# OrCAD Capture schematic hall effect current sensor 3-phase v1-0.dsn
size B; title: 3-Phase Hall Effect Current Sensor; rev: 1; note: XM3 Dual Inverter
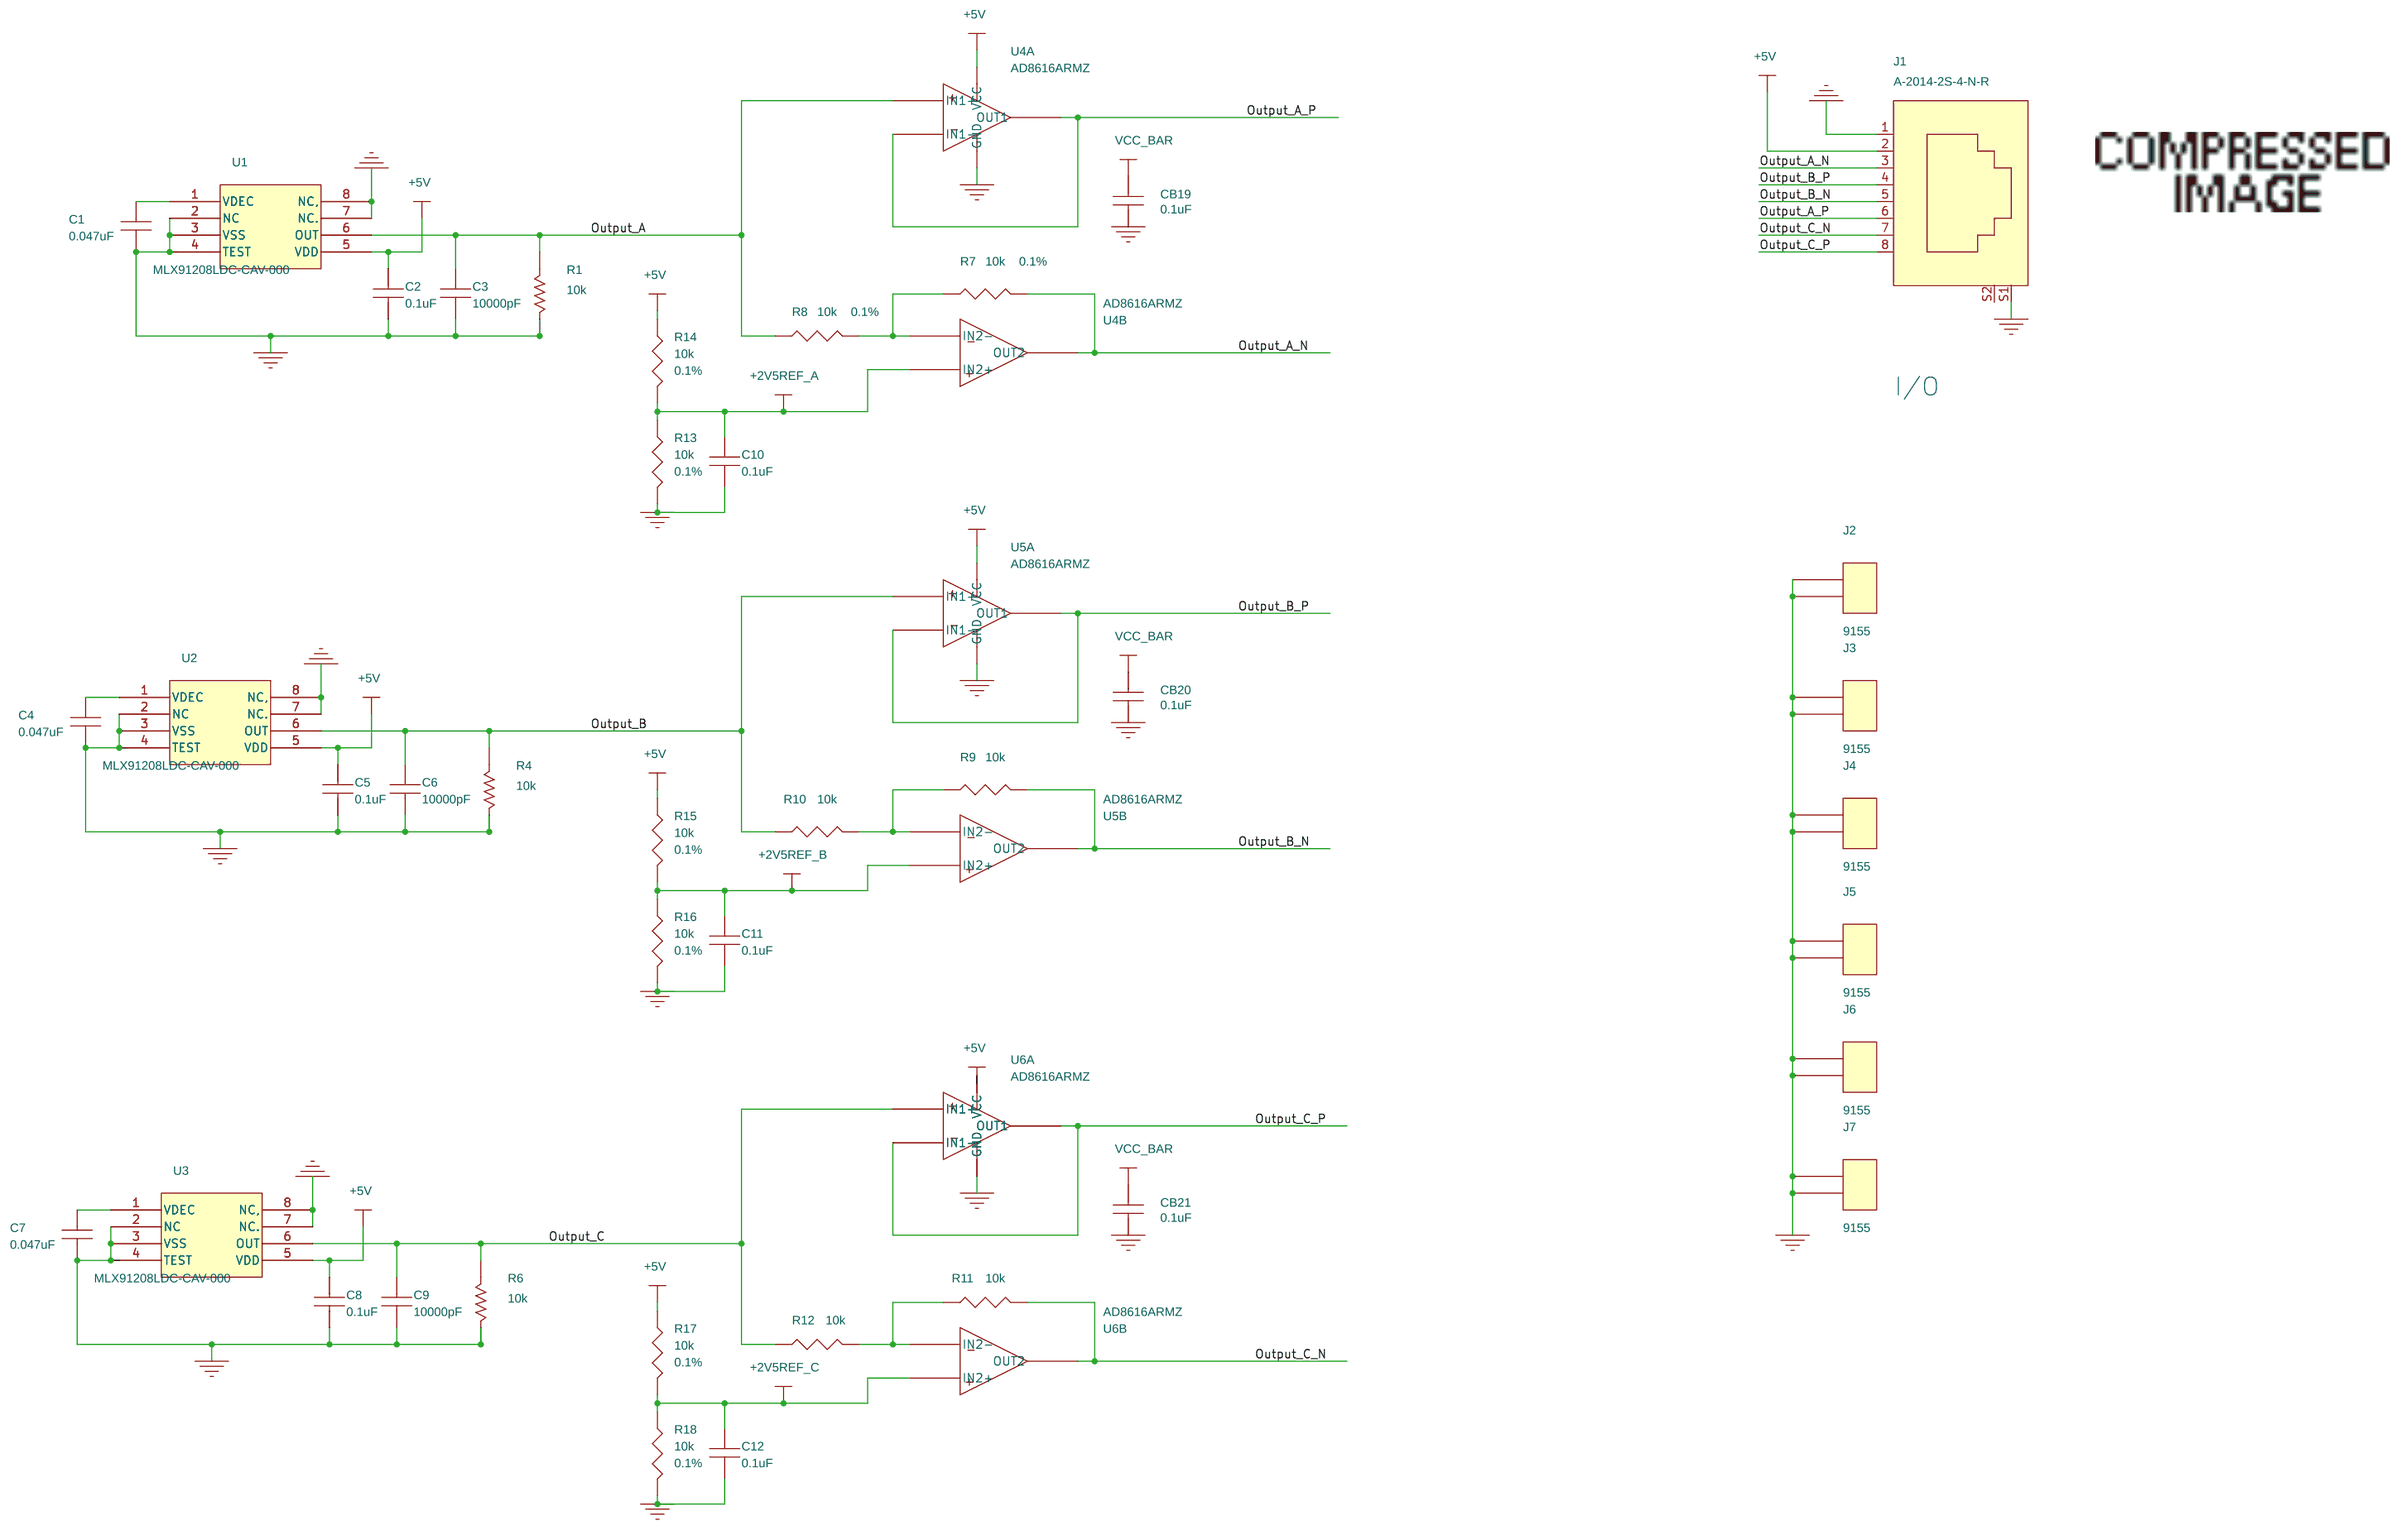
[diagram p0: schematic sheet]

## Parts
C1  0.047uF  [CAPC1608X90N]
C2  0.1uF  [CAPC1608X87N]
C3  10000pF  [CAPC1608X90N]
C4  0.047uF  [CAPC1608X90N]
C5  0.1uF  [CAPC1608X87N]
C6  10000pF  [CAPC1608X90N]
C7  0.047uF  [CAPC1608X90N]
C8  0.1uF  [CAPC1608X87N]
C9  10000pF  [CAPC1608X90N]
C10  0.1uF  [CAPC1608X87N]
C11  0.1uF  [CAPC1608X87N]
C12  0.1uF  [CAPC1608X87N]
CB19  0.1uF  [CAPC1608X87N]
CB20  0.1uF  [CAPC1608X87N]
CB21  0.1uF  [CAPC1608X87N]
J1  A-2014-2S-4-N-R  [RJ45_VERT_SHIELD_CON]
J2  9155  [AVX_9155_MOBO_2PIN]
J3  9155  [AVX_9155_MOBO_2PIN]
J4  9155  [AVX_9155_MOBO_2PIN]
J5  9155  [AVX_9155_MOBO_2PIN]
J6  9155  [AVX_9155_MOBO_2PIN]
J7  9155  [AVX_9155_MOBO_2PIN]
R1  10k  [RESC1608X55N]
R4  10k  [RESC1608X55N]
R6  10k  [RESC1608X55N]
R7  10k  [RESC1608X55N]
R8  10k  [RESC1608X55N]
R9  10k  [RESC1608X55N]
R10  10k  [RESC1608X55N]
R11  10k  [RESC1608X55N]
R12  10k  [RESC1608X55N]
R13  10k  [RESC1608X55N]
R14  10k  [RESC1608X55N]
R15  10k  [RESC1608X55N]
R16  10k  [RESC1608X55N]
R17  10k  [RESC1608X55N]
R18  10k  [RESC1608X55N]
U1  MLX91208LDC-CAV-000  [SOIC_8]
U2  MLX91208LDC-CAV-000  [SOIC_8]
U3  MLX91208LDC-CAV-000  [SOIC_8]
U4  AD8616ARMZ  [msop8_0_65x4_40p_h1_10]  (sections A,B)
U5  AD8616ARMZ  [msop8_0_65x4_40p_h1_10]  (sections A,B)
U6  AD8616ARMZ  [msop8_0_65x4_40p_h1_10]  (sections A,B)

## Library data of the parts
C1 C4 C7 = CAP: CAP CER 0.047UF 50V X7R 0603; CLASS: DISCRETE; Company Part Status: New; Manufacturer: Yageo; Manufacturer PN: CC0603KRX7R9BB473; PART_NUMBER: TMP-1661; Package Size: 0603 (1608 Metric); Rated Voltage: 50V; Temperature Coefficient: X7R; Tolerance: 10%
C2 C5 C8 C10-C12 CB19-CB21 = CAP: CAP CER 0.1UF 25V X7R 0603; CLASS: DISCRETE; Company Part Status: New; Dielectric Type: Capacitors; Manufacturer: Kemet; Manufacturer PN: C0603C104K3RACTU; PART_NUMBER: TMP-847; Package Size: 0603 (1608 Metric); Rated Voltage: 25V; Temperature Coefficient: X7R; Tolerance: 10%
C3 C6 C9 = CAP: CAP CER 10000PF 25V 10% X7R 0603; CLASS: DISCRETE; Company Part Status: New; Dielectric Type: Capacitors; Manufacturer: Samsung Electro-Mechanics America, Inc.; Manufacturer PN: CL10B103KA8NNNC; PART_NUMBER: TMP-566; Package Size: 0603 (1608 Metric); Rated Voltage: 25V; Temperature Coefficient: X7R; Tolerance: 10%
J1 = ModularJack8P8C-shielded: CONN MOD JACK 8P8C VERT SHIELDED; CLASS: IO; Company Part Status: New; Contact Voltage: 150V; Manufacturer: Assmann WSW Components; PART_NUMBER: TMP-1660
J2-J7 = CON2: CONN SPRING BATTERY 2POS R/A SMD; CLASS: IO; Company Part Status: New; Manufacturer: AVX Corporation; Manufacturer PN: 009155002541006; PART_NUMBER: TMP-1669
R1 R4 R6 = RES_0: RES SMD 10K OHM 1% 1/10W 0603; CLASS: DISCRETE; Company Part Status: New; Manufacturer: Panasonic Electronic Components; Manufacturer PN: ERJ-3EKF1002V; PART_NUMBER: TMP-788; Package Size: 0603 (1608 Metric); Rated Power: 0.1W, 1/10W; Temperature Coefficient: 100ppm/C; Tolerance: 1%
R7-R18 = R: RES SMD 10K OHM 0.1% 1/16W 0603; CLASS: DISCRETE; Company Part Status: New; Manufacturer: TE Connectivity Passive Product; Manufacturer PN: CPF0603B10KE; PART_NUMBER: TMP-1663; Package Size: 0603 (1608 Metric); Rated Power: 0.063W, 1/16W; Temperature Coefficient: 25ppm/C; Tolerance: 0.1%
U1-U3 = MLX91208: SENSOR CURRENT HALL 40MT AC/DC; CLASS: IC; Company Part Status: New; Manufacturer: Melexis Technologies NV; Manufacturer PN: MLX91208LDC-CAV-000-SP; PART_NUMBER: TMP-1764; Package Size: 8-SOIC (0.154", 3.90mm Width); Supply Voltage: 4.5V ~ 5.5V
U4-U6 = OPAMP_2X_8P: IC OPAMP GP 24MHZ RRO 8MSOP; CLASS: IC; Company Part Status: New; Manufacturer: Analog Devices Inc.; Manufacturer PN: AD8616ARMZ-REEL; PART_NUMBER: TMP-1500; Package Size: 8-TSSOP, 8-MSOP (0.118", 3.00mm Width); Supply Voltage: 2.7 V - 5.5 V, 1.35 V - 2.75 V

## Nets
+2V5REF_A: C10.1 R13.1 R14.2 U4.5(IN2+)
+2V5REF_B: C11.1 R15.2 R16.1 U5.5(IN2+)
+2V5REF_C: C12.1 R17.2 R18.1 U6.5(IN2+)
+5V: C2.1 C5.1 C8.1 CB19.1 CB20.1 CB21.1 J1.2 R14.1 R15.1 R17.1 U1.5(VDD) U2.5(VDD) U3.5(VDD) U4.8(VCC) U5.8(VCC) U6.8(VCC)
0: C1.2 C2.2 C3.2 C4.2 C5.2 C6.2 C7.2 C8.2 C9.2 C10.2 C11.2 C12.2 CB19.2 CB20.2 CB21.2 J1.1 J1.S1(SHIELD) J2.1 J2.2 J3.1 J3.2 J4.1 J4.2 J5.1 J5.2 J6.1 J6.2 J7.1 J7.2 R1.1 R4.1 R6.1 R13.2 R16.2 R18.2 U1.2(NC) U1.3(VSS) U1.4(TEST) U1.7(NC.) U1.8(NC,) U2.2(NC) U2.3(VSS) U2.4(TEST) U2.7(NC.) U2.8(NC,) U3.2(NC) U3.3(VSS) U3.4(TEST) U3.7(NC.) U3.8(NC,) U4.4(GND) U5.4(GND) U6.4(GND)
Output_A: C3.1 R1.2 R8.1 U1.6(OUT) U4.3(IN1+)
Output_A_N: J1.3 R7.2 U4.7(OUT2)
Output_A_P: J1.6 U4.1(OUT1) U4.2(IN1-)
Output_B: C6.1 R4.2 R10.1 U2.6(OUT) U5.3(IN1+)
Output_B_N: J1.5 R9.2 U5.7(OUT2)
Output_B_P: J1.4 U5.1(OUT1) U5.2(IN1-)
Output_C: C9.1 R6.2 R12.1 U3.6(OUT) U6.3(IN1+)
Output_C_N: J1.7 R11.2 U6.7(OUT2)
Output_C_P: J1.8 U6.1(OUT1) U6.2(IN1-)
N4844729: C1.1 U1.1(VDEC)
N4845886: C4.1 U2.1(VDEC)
N4846468: C7.1 U3.1(VDEC)
N4848257: R7.1 R8.2 U4.6(IN2-)
N4851782: R9.1 R10.2 U5.6(IN2-)
N4852376: R11.1 R12.2 U6.6(IN2-)

Not connected (* = marked no-connect by the designer): J1 S2(SHIELD2)

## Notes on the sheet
- I/O
